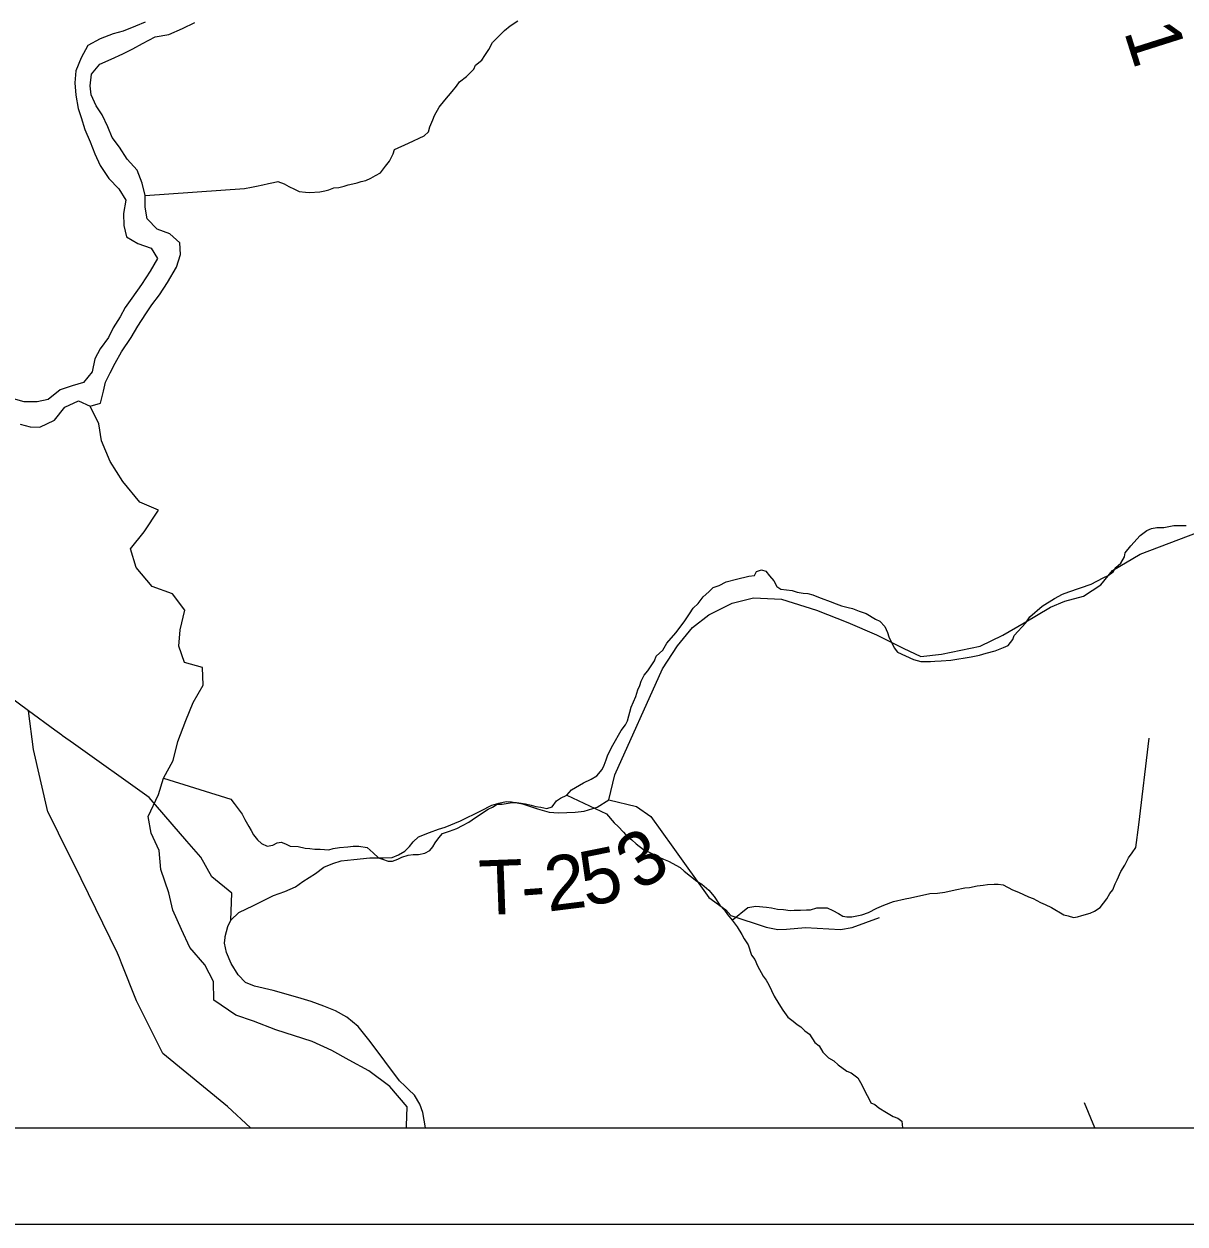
# Model space of a CAD drawing. Extents: x 0 to 34, y 0 to 22.
# Drawn here: x 5.45 to 6.659, y 14 to 15.248 of the extents above; entities that cross this region are included whole.
import ezdxf

# ---------------------------------------------------------------- set-up
doc = ezdxf.new("R2010")
doc.units = 0
for name, color, linetype in [('GM_X_Major_River', 7, 'Continuous'), ('GM_X_Minor_River', 7, 'Continuous'), ('GM_X_Township_Road', 7, 'Continuous'), ('GM_X_Township_Road_Text', 7, 'Continuous'), ('SH_Data', 7, 'Continuous')]:
    doc.layers.add(name, color=color, linetype=linetype)

msp = doc.modelspace()

# ---------------------------------------------------------------- linework, layer by layer
at = {"layer": 'GM_X_Major_River'}
for points in [[(5.5764, 15.2501), (5.5662, 15.246), (5.5533, 15.241), (5.5431, 15.238), (5.5295, 15.2331), (5.5167, 15.2259), (5.5095, 15.213), (5.5042, 15.1997), (5.5031, 15.1872), (5.5042, 15.1743), (5.5065, 15.1606), (5.5095, 15.1512), (5.5136, 15.1386), (5.5189, 15.1258), (5.5238, 15.1132), (5.5295, 15.1011), (5.5386, 15.0878), (5.5488, 15.0769), (5.556, 15.0651), (5.5537, 15.0511), (5.5541, 15.0389), (5.5567, 15.0268), (5.5688, 15.02), (5.5824, 15.0151), (5.5892, 15.0044), (5.5816, 14.9912), (5.5726, 14.9775), (5.5624, 14.9631), (5.5555, 14.9536), (5.5503, 14.9438), (5.5431, 14.9324), (5.5382, 14.9221), (5.5295, 14.9104), (5.5238, 14.9001), (5.5211, 14.8865), (5.5121, 14.8755), (5.5003, 14.8721), (5.4879, 14.8679), (5.4754, 14.8577), (5.4637, 14.8554), (5.4504, 14.8554), (5.4368, 14.8592)], [(5.4463, 14.8319), (5.4565, 14.8292), (5.4667, 14.8288), (5.4818, 14.8364), (5.4928, 14.8497), (5.5068, 14.8562), (5.5189, 14.8508), (5.5298, 14.8539), (5.5328, 14.8664), (5.5351, 14.8759), (5.54, 14.8854), (5.545, 14.8956), (5.5518, 14.9074), (5.5616, 14.9222), (5.5688, 14.9339), (5.5771, 14.9468), (5.5831, 14.9563), (5.5911, 14.9665), (5.5994, 14.9794), (5.6089, 14.9954), (5.613, 15.0086), (5.6123, 15.0208), (5.6021, 15.0299), (5.5888, 15.0348), (5.5782, 15.0458), (5.5764, 15.0579), (5.5764, 15.07), (5.5733, 15.0829), (5.5681, 15.0962), (5.5575, 15.1076), (5.5495, 15.1201), (5.542, 15.1303), (5.5374, 15.1413), (5.5314, 15.1538), (5.5254, 15.1633), (5.5201, 15.1747), (5.5189, 15.1841), (5.5205, 15.1963), (5.5291, 15.2065), (5.5409, 15.2118), (5.553, 15.2172), (5.5635, 15.2225), (5.5734, 15.2282), (5.5866, 15.235), (5.601, 15.2376), (5.615, 15.2437), (5.6278, 15.2498)]]:
    msp.add_lwpolyline(points, dxfattribs=at)
at = {"layer": 'GM_X_Minor_River'}
msp.add_line((6.5646, 14.1), (6.554, 14.1262), dxfattribs=at)
for points in [[(5.5764, 15.07), (5.6795, 15.0771), (5.6871, 15.0785), (5.6921, 15.0795), (5.6989, 15.0809), (5.7046, 15.0823), (5.7099, 15.0834), (5.7145, 15.0845), (5.7209, 15.0821), (5.7258, 15.0793), (5.7318, 15.0766), (5.7366, 15.0742), (5.7431, 15.0733), (5.7472, 15.0729), (5.7579, 15.0738), (5.7632, 15.0749), (5.7674, 15.076), (5.7727, 15.0778), (5.778, 15.0784), (5.7833, 15.0795), (5.7875, 15.0809), (5.7925, 15.082), (5.797, 15.0831), (5.8012, 15.0845), (5.8058, 15.0856), (5.8111, 15.0881), (5.8161, 15.0907), (5.8211, 15.0937), (5.8265, 15.1004), (5.8304, 15.1057), (5.8343, 15.1132), (5.8359, 15.1177), (5.8504, 15.1243), (5.8665, 15.132), (5.8711, 15.1361), (5.8727, 15.1414), (5.8755, 15.1486), (5.8774, 15.1531), (5.8821, 15.1617), (5.8883, 15.1692), (5.8957, 15.1782), (5.9003, 15.1838), (5.9034, 15.1883), (5.9107, 15.1939), (5.9184, 15.2014), (5.92, 15.2055), (5.9265, 15.2107), (5.9297, 15.2156), (5.9339, 15.222), (5.9379, 15.2291), (5.9433, 15.2347), (5.9502, 15.2415), (5.956, 15.2463), (5.964, 15.2515)], [(5.6478, 14.233), (5.6475, 14.2521), (5.6385, 14.2696), (5.6226, 14.2875), (5.614, 14.3065), (5.6049, 14.3266), (5.6008, 14.3445), (5.5925, 14.3688), (5.5907, 14.3886), (5.5824, 14.4065), (5.5794, 14.424), (5.5901, 14.4468), (5.5954, 14.4639), (5.6053, 14.4821), (5.6103, 14.5019), (5.6186, 14.5239), (5.6262, 14.5426), (5.6365, 14.5604), (5.6358, 14.579), (5.6173, 14.584), (5.6112, 14.6011), (5.6128, 14.6182), (5.6174, 14.6384), (5.6046, 14.6555), (5.5834, 14.6631), (5.5668, 14.6829), (5.5611, 14.7023), (5.5752, 14.7201), (5.59, 14.7426), (5.5707, 14.7509), (5.553, 14.7723), (5.5398, 14.7932), (5.5307, 14.8149), (5.5281, 14.8323), (5.5189, 14.8508)], [(6.2046, 14.674), (6.2103, 14.6747), (6.2126, 14.6788), (6.2176, 14.6806), (6.2221, 14.679), (6.2262, 14.6744), (6.2306, 14.669), (6.2336, 14.6632), (6.238, 14.6605), (6.2437, 14.6597), (6.2498, 14.6592), (6.255, 14.6572), (6.2611, 14.6563), (6.266, 14.6559), (6.2713, 14.6546), (6.2754, 14.6527), (6.2799, 14.6511), (6.2893, 14.6475), (6.2954, 14.6451), (6.301, 14.6431), (6.3078, 14.6415), (6.3123, 14.6403), (6.3195, 14.6375), (6.3266, 14.6351), (6.3364, 14.6292), (6.3409, 14.6272), (6.3461, 14.6215), (6.349, 14.6153), (6.3504, 14.6108), (6.3559, 14.5993), (6.3592, 14.595), (6.3758, 14.5872), (6.3837, 14.5851), (6.3882, 14.585), (6.3935, 14.5853), (6.3981, 14.5856), (6.4049, 14.5859), (6.4148, 14.5865), (6.436, 14.5899), (6.4448, 14.5917), (6.4516, 14.5938), (6.4608, 14.5963), (6.4695, 14.5996), (6.4745, 14.6018), (6.4795, 14.6082), (6.4807, 14.6123), (6.4927, 14.6254), (6.497, 14.6318), (6.5097, 14.6426), (6.5227, 14.6507), (6.5311, 14.6551), (6.5376, 14.6577), (6.5609, 14.6657), (6.5735, 14.6723), (6.5784, 14.6745), (6.5838, 14.6786), (6.5865, 14.6831), (6.5919, 14.6875), (6.5954, 14.6939), (6.5963, 14.6981), (6.6021, 14.7056), (6.6117, 14.7161), (6.6187, 14.7216), (6.6236, 14.7234), (6.6293, 14.7245), (6.6365, 14.7247), (6.6468, 14.7268), (6.6596, 14.7266)], [(5.5954, 14.4639), (5.6653, 14.442), (5.669, 14.4374), (5.6731, 14.432), (5.6771, 14.4263), (5.6801, 14.4209), (5.6841, 14.4136), (5.6867, 14.4094), (5.6889, 14.4048), (5.6933, 14.3998), (5.6974, 14.3959), (5.7031, 14.3932), (5.7091, 14.3942), (5.7137, 14.3964), (5.7179, 14.3971), (5.7224, 14.3955), (5.7273, 14.3931), (5.7356, 14.3926), (5.7428, 14.391), (5.7477, 14.3905), (5.753, 14.39), (5.7583, 14.3899), (5.7674, 14.3894), (5.772, 14.3905), (5.7784, 14.3915), (5.7871, 14.3925), (5.7928, 14.3932), (5.7985, 14.3931), (5.8072, 14.3918), (5.8135, 14.386), (5.8191, 14.3809), (5.8233, 14.3797), (5.8293, 14.3773), (5.8338, 14.3773), (5.8392, 14.3795), (5.8434, 14.3817), (5.8499, 14.3838), (5.8552, 14.3845), (5.8609, 14.3844), (5.8673, 14.3858), (5.8727, 14.3884), (5.8758, 14.3925), (5.8781, 14.3966), (5.882, 14.4019), (5.8859, 14.4064), (5.8931, 14.4085), (5.9007, 14.4115), (5.9065, 14.4144), (5.9133, 14.4181), (5.9202, 14.4229), (5.9333, 14.4314), (5.9379, 14.4336), (5.9428, 14.4366), (5.9478, 14.4369), (5.9584, 14.4386), (5.9626, 14.4385), (5.9675, 14.4377), (5.972, 14.4372), (5.978, 14.4356), (5.9829, 14.4344), (5.9882, 14.4335), (5.9943, 14.4323), (6, 14.4341), (6.0043, 14.4401), (6.0085, 14.443), (6.0153, 14.446), (6.02, 14.4516), (6.0326, 14.459), (6.0403, 14.4626), (6.0464, 14.4663), (6.0518, 14.4727), (6.0541, 14.4772), (6.0561, 14.4829), (6.0578, 14.4881), (6.0629, 14.4983), (6.0718, 14.5133), (6.0761, 14.5193), (6.0784, 14.5235), (6.0821, 14.5375), (6.0868, 14.5488), (6.0892, 14.5556), (6.0912, 14.5601), (6.0924, 14.5646), (6.0956, 14.571), (6.0994, 14.5755), (6.1064, 14.586), (6.108, 14.5906), (6.115, 14.5969), (6.1193, 14.6044), (6.1285, 14.6149), (6.1371, 14.6265), (6.1429, 14.6348), (6.1468, 14.6408), (6.1518, 14.6456), (6.1572, 14.6524), (6.163, 14.6576), (6.1676, 14.6621), (6.1737, 14.6643), (6.181, 14.6679), (6.1916, 14.6708), (6.2046, 14.674)], [(6.1873, 14.3162), (6.2034, 14.3292), (6.2118, 14.3306), (6.2231, 14.3296), (6.228, 14.3288), (6.2345, 14.3276), (6.2405, 14.3271), (6.2477, 14.3262), (6.2519, 14.3265), (6.2583, 14.3264), (6.2647, 14.3267), (6.2689, 14.327), (6.2754, 14.3288), (6.2807, 14.329), (6.286, 14.329), (6.292, 14.3262), (6.298, 14.3231), (6.3025, 14.3203), (6.3067, 14.3195), (6.3116, 14.3194), (6.3222, 14.3215), (6.3291, 14.324), (6.3379, 14.3285), (6.3451, 14.3317), (6.355, 14.3354), (6.3672, 14.3382), (6.3729, 14.3392), (6.3931, 14.3438), (6.401, 14.3441), (6.4086, 14.3451), (6.4193, 14.3476), (6.4295, 14.3497), (6.4341, 14.35), (6.4421, 14.3517), (6.4485, 14.3524), (6.4531, 14.3531), (6.4599, 14.3537), (6.4641, 14.3536), (6.4694, 14.3528), (6.4791, 14.3477), (6.4851, 14.3453), (6.4957, 14.3402), (6.5005, 14.3386), (6.508, 14.3343), (6.5129, 14.3323), (6.5197, 14.3292), (6.5324, 14.3217), (6.537, 14.3205), (6.5426, 14.3189), (6.5468, 14.3196), (6.551, 14.321), (6.5597, 14.3235), (6.5643, 14.3254), (6.5701, 14.3294), (6.5771, 14.3384), (6.5802, 14.3437), (6.5833, 14.3478), (6.586, 14.3538), (6.588, 14.358), (6.5916, 14.3667), (6.5959, 14.3734), (6.5998, 14.381), (6.6037, 14.3862), (6.6072, 14.3918), (6.6106, 14.4153), (6.6213, 14.5055)], [(6.0153, 14.446), (6.0563, 14.4267), (6.0645, 14.4174), (6.0686, 14.4135), (6.0741, 14.4077), (6.0782, 14.4027), (6.0827, 14.3996), (6.0872, 14.3954), (6.095, 14.3895), (6.1044, 14.3852), (6.1112, 14.3817), (6.1157, 14.3797), (6.1209, 14.3773), (6.133, 14.371), (6.1371, 14.3672), (6.1438, 14.3617), (6.1505, 14.3567), (6.1558, 14.3536), (6.1628, 14.3474), (6.1684, 14.3408), (6.1743, 14.3316), (6.1791, 14.3266), (6.1825, 14.322), (6.1873, 14.3162), (6.1925, 14.3093), (6.1973, 14.3012), (6.1998, 14.2966), (6.2039, 14.2905), (6.2075, 14.2798), (6.2108, 14.2752), (6.2137, 14.2687), (6.2196, 14.2579), (6.2226, 14.2537), (6.2255, 14.2487), (6.228, 14.243), (6.231, 14.2369), (6.2358, 14.2292), (6.2398, 14.2223), (6.245, 14.215), (6.2506, 14.2111), (6.2547, 14.2076), (6.2588, 14.2052), (6.2629, 14.201), (6.2678, 14.1975), (6.2733, 14.1887), (6.2778, 14.1852), (6.2815, 14.1787), (6.2874, 14.1729), (6.293, 14.1697), (6.2975, 14.1655), (6.3065, 14.1589), (6.311, 14.1573), (6.3181, 14.1522), (6.3221, 14.1449), (6.3262, 14.1361), (6.3291, 14.1311), (6.3317, 14.1262), (6.3358, 14.1242), (6.3399, 14.1207), (6.3478, 14.116), (6.3549, 14.1117), (6.3598, 14.1101), (6.3639, 14.107), (6.3645, 14.1)], [(5.8481, 14.1), (5.8483, 14.1022), (5.8491, 14.1219), (5.831, 14.1432), (5.8091, 14.1592), (5.7887, 14.1706), (5.7706, 14.1805), (5.7502, 14.1897), (5.7123, 14.2019), (5.6889, 14.2111), (5.6708, 14.2172), (5.6478, 14.233)]]:
    msp.add_lwpolyline(points, dxfattribs=at)
at = {"layer": 'GM_X_Township_Road'}
for points in [[(5.6656, 14.3162), (5.6738, 14.3241), (5.6891, 14.3313), (5.7099, 14.3419), (5.7215, 14.3459), (5.7329, 14.3508), (5.7403, 14.3563), (5.7535, 14.3647), (5.7621, 14.3711), (5.7715, 14.3751), (5.7802, 14.3778), (5.7933, 14.3793), (5.8101, 14.3808), (5.8243, 14.381), (5.8332, 14.3813), (5.8401, 14.384), (5.8465, 14.388), (5.8515, 14.3927), (5.8552, 14.3976), (5.8606, 14.4028), (5.8723, 14.4073), (5.8814, 14.4107), (5.8886, 14.4127), (5.9045, 14.4194), (5.9256, 14.4297), (5.937, 14.4357), (5.9444, 14.4379), (5.9521, 14.4394), (5.9577, 14.4392), (5.969, 14.4372), (5.9847, 14.4318), (5.9968, 14.4284), (6.0065, 14.4277), (6.0239, 14.4284), (6.0333, 14.4293), (6.0468, 14.4335), (6.0588, 14.4412), (6.065, 14.4671), (6.1147, 14.5774), (6.1303, 14.6013), (6.1458, 14.6207), (6.1629, 14.6336), (6.1873, 14.6457), (6.2093, 14.6514), (6.2385, 14.6499), (6.275, 14.6385), (6.3076, 14.6259), (6.3376, 14.613), (6.3653, 14.599), (6.3836, 14.5902), (6.4052, 14.5929), (6.4455, 14.6012), (6.469, 14.6126), (6.4911, 14.6255), (6.5184, 14.6418), (6.5333, 14.6479), (6.553, 14.6532), (6.5709, 14.6649), (6.583, 14.6797), (6.6117, 14.6969), (6.6822, 14.7235)], [(5.4903, 14.508), (5.4895, 14.5086), (5.4821, 14.5139), (5.4548, 14.534), (5.36, 14.604), (5.3119, 14.6481), (5.2467, 14.6996)], [(5.4861, 14.4065), (5.4835, 14.4117), (5.4749, 14.4288), (5.46, 14.4936), (5.4548, 14.534)], [(5.6198, 14.3984), (5.5803, 14.4438), (5.5017, 14.4999), (5.4903, 14.508)], [(6.0588, 14.4412), (6.0875, 14.4342), (6.1024, 14.4238), (6.1139, 14.4079), (6.1253, 14.3921), (6.1629, 14.3396), (6.1808, 14.3267), (6.1858, 14.3208), (6.2225, 14.3089), (6.2349, 14.3064), (6.2439, 14.3068), (6.2637, 14.3083), (6.3, 14.3063), (6.3122, 14.3085), (6.3407, 14.3187)], [(5.5518, 14.2714), (5.5497, 14.2768), (5.5473, 14.2818), (5.5098, 14.359), (5.4861, 14.4065)], [(5.6596, 14.2981), (5.6597, 14.299), (5.6624, 14.3095), (5.6656, 14.3162), (5.6663, 14.3442), (5.6458, 14.3612), (5.6343, 14.3817), (5.6198, 14.3984)], [(5.8504, 14.14), (5.847, 14.1433), (5.841, 14.149), (5.8106, 14.1899), (5.7978, 14.2053), (5.7861, 14.215), (5.7745, 14.2217), (5.7621, 14.2266), (5.7492, 14.2316), (5.7351, 14.2358), (5.7094, 14.2429), (5.6901, 14.2474), (5.6807, 14.2514), (5.673, 14.2593), (5.6658, 14.2709), (5.6609, 14.2825), (5.6589, 14.2922), (5.6596, 14.2981)], [(5.6859, 14.1), (5.6618, 14.1224), (5.5945, 14.1772), (5.5671, 14.232), (5.5518, 14.2714)], [(5.8679, 14.1), (5.8653, 14.116), (5.8621, 14.1248), (5.8566, 14.1339), (5.8504, 14.14)]]:
    msp.add_lwpolyline(points, dxfattribs=at)
at = {"layer": 'SH_Data'}
for p, q in [((2.1, 14.1), (8.9, 14.1)), ((2, 14), (9, 14))]:
    msp.add_line(p, q, dxfattribs=at)

# ---------------------------------------------------------------- texts
at = {"layer": 'GM_X_Township_Road_Text'}
for s, rotation, p in [('1', 287.6091, (6.5947, 15.2408)), ('3', 32.0494, (6.0899, 14.3452)), ('2', 7.0637, (5.9956, 14.3249)), ('5', 11.452, (6.035, 14.33)), ('T', 2.0736, (5.9245, 14.3213)), ('-', 4.1819, (5.9692, 14.3229))]:
    msp.add_text(s, height=0.0568, rotation=rotation, dxfattribs=at).set_placement(p)

doc.saveas('drawing.dxf')
